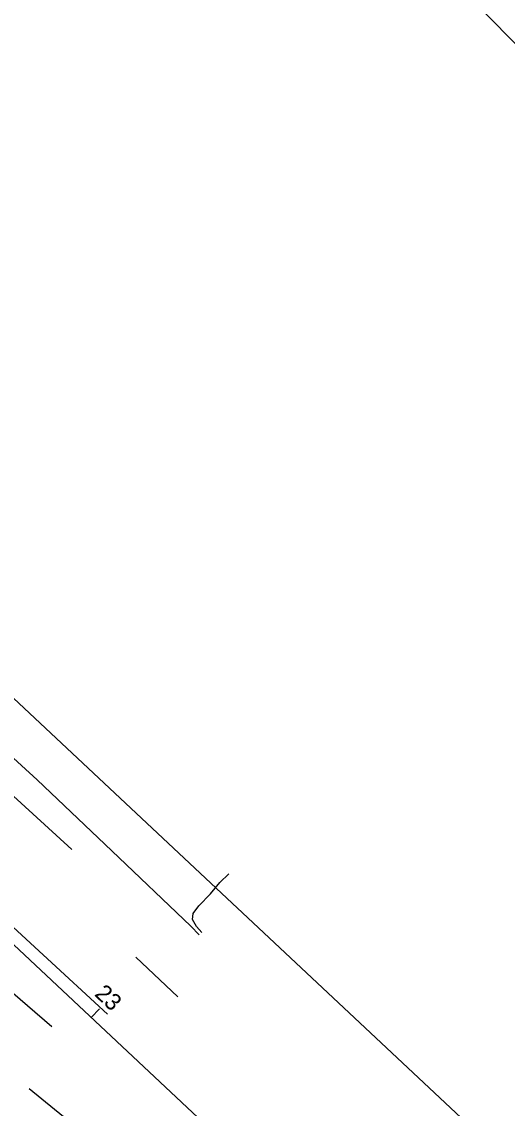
# Model space of a CAD drawing. Extents: x 1475900 to 1484331, y 375914 to 383395.
# Drawn here: x 1479789.2 to 1479870.3, y 379755.2 to 379936.7 of the extents above; entities that cross this region are included whole.
import ezdxf

# ---------------------------------------------------------------- set-up
doc = ezdxf.new("R2010")
doc.units = 0
for name, color, linetype in [('PM_X_CL_Double_Solid', 7, 'Continuous'), ('PM_X_Lane_Line', 7, 'Continuous'), ('PV_X_Curb', 7, 'Continuous'), ('RW_X_CL_20', 7, 'Continuous'), ('RW_X_Esmt_SH', 7, 'Continuous'), ('RW_X_Esmt_U', 7, 'Continuous'), ('RW_X_Text', 7, 'Continuous')]:
    doc.layers.add(name, color=color, linetype=linetype)

msp = doc.modelspace()

# ---------------------------------------------------------------- linework, layer by layer
at = {"layer": 'PM_X_CL_Double_Solid'}
for points in [[(1479794.22, 379768.77), (1479779.09, 379781.77), (1479763.16, 379795.43), (1479746.62, 379810.62), (1479732.24, 379823.87), (1479714.72, 379840.65), (1479700.71, 379853.61), (1479677.93, 379875.07)], [(1479803.53, 379770.9), (1479781.95, 379790.71), (1479777.89, 379794.07), (1479768.81, 379800.57), (1479752.35, 379810.89), (1479732.76, 379823.63)]]:
    msp.add_lwpolyline(points, dxfattribs=at)
at = {"layer": 'PM_X_Lane_Line'}
for p, q in [((1479815.25, 379773.81), (1479808.25, 379780.44)), ((1479798.26, 379752.01), (1479790.42, 379758.43))]:
    msp.add_line(p, q, dxfattribs=at)
at = {"layer": 'PV_X_Curb'}
for points in [[(1479818.81, 379784.12), (1479817.44, 379785.58), (1479804.23, 379798.17), (1479791.74, 379810.03), (1479778.64, 379821.98)], [(1479819.26, 379784.56), (1479818.41, 379785.52), (1479817.73, 379786.71), (1479817.84, 379787.69), (1479818.76, 379788.98), (1479820.72, 379791.01), (1479822.31, 379792.9), (1479823.77, 379794.35)]]:
    msp.add_lwpolyline(points, dxfattribs=at)
at = {"layer": 'RW_X_CL_20'}
msp.add_line((1479800.81, 379770.35), (1479802.18, 379771.81), dxfattribs=at)
msp.add_lwpolyline([(1477185.15, 382318.79), (1478151.68, 381373.49), (1479566.7, 379989.54), (1480555.97, 379063.33), (1481343.87, 378335.5), (1481853.32, 377853.22), (1482587.9, 377143.51), (1482849.67, 376882.07), (1483668.91, 376080.34), (1483878.1, 376026.7), (1484025.82, 375988.83), (1484313.71, 375915.02)], dxfattribs=at)
at = {"layer": 'RW_X_Esmt_SH'}
msp.add_line((1479687.35, 379917.68), (1479967.32, 379655.56), dxfattribs=at)
at = {"layer": 'RW_X_Esmt_U'}
msp.add_line((1479806.63, 379999.17), (1479951.46, 379851.77), dxfattribs=at)
at = {"layer": 'RW_X_Text'}
msp.add_lwpolyline([(1479797.55, 379798.42), (1479779.29, 379815.04), (1479755.95, 379837.17), (1479710.6, 379878.47), (1479700.46, 379887.97), (1479695.14, 379892.26), (1479687.63, 379898.54), (1479684.65, 379909.71), (1479684.09, 379918.26), (1479685.98, 379925.49), (1479693.36, 379933.84), (1479703.54, 379940.07), (1479719.59, 379947.28), (1479755.69, 379965.71), (1479770.46, 379973.23)], dxfattribs=at)

# ---------------------------------------------------------------- texts
at = {"layer": 'RW_X_CL_20'}
msp.add_text('23', height=2.8, rotation=316.8859, dxfattribs=at).set_placement((1479801.21, 379774.09))

doc.saveas('drawing.dxf')
